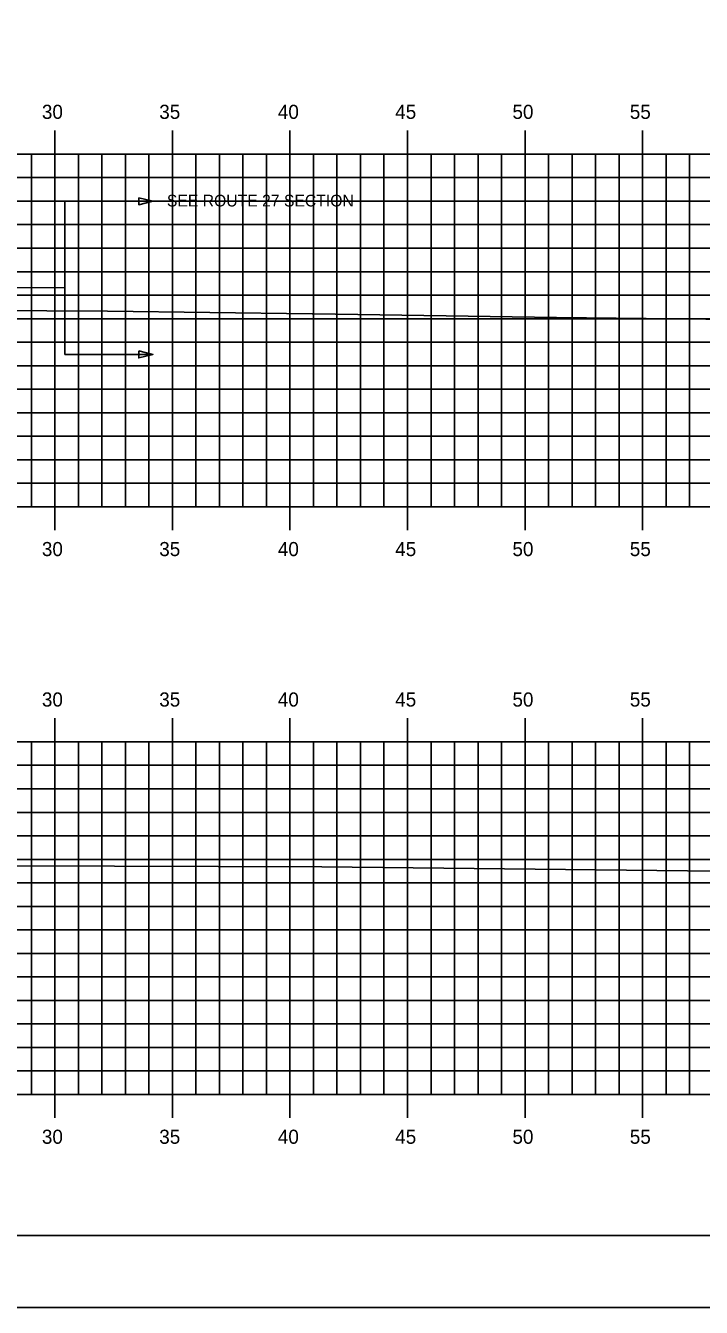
# Model space of a CAD drawing. Extents: x 1048109 to 1048279, y 781630 to 781740.
# Drawn here: x 1048220.5 to 1048249.2, y 781630.1 to 781684.7 of the extents above; entities that cross this region are included whole.
import ezdxf

# ---------------------------------------------------------------- set-up
doc = ezdxf.new("R2010")
doc.units = 0
for name, color, linetype in [('ANNOTATION', 7, 'Continuous'), ('D_Roadway_Centerline', 7, 'Continuous'), ('Default', 7, 'Continuous'), ('H_V ANNOTATION', 7, 'Continuous'), ('MAJOR', 7, 'Continuous'), ('MINOR', 7, 'Continuous'), ('S_Roadway_Centerline', 7, 'Continuous')]:
    doc.layers.add(name, color=color, linetype=linetype)

msp = doc.modelspace()

# ---------------------------------------------------------------- linework, layer by layer
at = {"layer": 'ANNOTATION'}
for p, q in [((1048225.901, 781677.193), (1048222.163, 781677.193)), ((1048225.901, 781670.675), (1048222.163, 781670.675))]:
    msp.add_line(p, q, dxfattribs=at)
for points in [[(1048225.301, 781677.343), (1048225.901, 781677.193), (1048225.301, 781677.043)], [(1048225.301, 781670.825), (1048225.901, 781670.675), (1048225.301, 781670.525)]]:
    msp.add_lwpolyline(points, close=True, dxfattribs=at)
at = {"layer": 'D_Roadway_Centerline'}
for p, q in [((1048222.163, 781670.675), (1048222.163, 781677.193)), ((1048191.733, 781673.663), (1048222.163, 781673.508))]:
    msp.add_line(p, q, dxfattribs=at)
at = {"layer": 'Default'}
msp.add_line((1048116.734, 781633.195), (1048276.734, 781633.195), dxfattribs=at)
msp.add_lwpolyline([(1048108.64, 781630.136), (1048278.64, 781630.136), (1048278.64, 781740.136), (1048108.64, 781740.136)], close=True, dxfattribs=at)
at = {"layer": 'MAJOR'}
for p, q in [((1048221.733, 781680.197), (1048221.733, 781679.195)), ((1048221.733, 781680.197), (1048221.733, 781679.195)), ((1048226.733, 781680.197), (1048226.733, 781679.195)), ((1048226.733, 781680.197), (1048226.733, 781679.195)), ((1048231.733, 781680.197), (1048231.733, 781679.195)), ((1048231.733, 781680.197), (1048231.733, 781679.195)), ((1048236.733, 781680.197), (1048236.733, 781679.195)), ((1048236.733, 781680.197), (1048236.733, 781679.195)), ((1048241.733, 781680.197), (1048241.733, 781679.195)), ((1048241.733, 781680.197), (1048241.733, 781679.195)), ((1048246.733, 781680.197), (1048246.733, 781679.195)), ((1048246.733, 781680.197), (1048246.733, 781679.195)), ((1048121.733, 781679.195), (1048261.733, 781679.195)), ((1048121.733, 781679.195), (1048261.733, 781679.195)), ((1048121.733, 781679.195), (1048261.733, 781679.195)), ((1048121.733, 781679.195), (1048261.733, 781679.195)), ((1048221.733, 781664.195), (1048221.733, 781679.195)), ((1048221.733, 781664.195), (1048221.733, 781679.195)), ((1048226.733, 781664.195), (1048226.733, 781679.195)), ((1048226.733, 781664.195), (1048226.733, 781679.195)), ((1048231.733, 781664.195), (1048231.733, 781679.195)), ((1048231.733, 781664.195), (1048231.733, 781679.195)), ((1048236.733, 781664.195), (1048236.733, 781679.195)), ((1048236.733, 781664.195), (1048236.733, 781679.195)), ((1048241.733, 781664.195), (1048241.733, 781679.195)), ((1048241.733, 781664.195), (1048241.733, 781679.195)), ((1048246.733, 781664.195), (1048246.733, 781679.195)), ((1048246.733, 781664.195), (1048246.733, 781679.195)), ((1048121.733, 781674.195), (1048261.733, 781674.195)), ((1048121.733, 781674.195), (1048261.733, 781674.195)), ((1048121.733, 781669.195), (1048261.733, 781669.195)), ((1048121.733, 781669.195), (1048261.733, 781669.195)), ((1048121.733, 781664.195), (1048261.733, 781664.195)), ((1048121.733, 781664.195), (1048261.733, 781664.195)), ((1048121.733, 781664.195), (1048261.733, 781664.195)), ((1048121.733, 781664.195), (1048261.733, 781664.195)), ((1048221.733, 781663.193), (1048221.733, 781664.195)), ((1048221.733, 781663.193), (1048221.733, 781664.195)), ((1048226.733, 781663.193), (1048226.733, 781664.195)), ((1048226.733, 781663.193), (1048226.733, 781664.195)), ((1048231.733, 781663.193), (1048231.733, 781664.195)), ((1048231.733, 781663.193), (1048231.733, 781664.195)), ((1048236.733, 781663.193), (1048236.733, 781664.195)), ((1048236.733, 781663.193), (1048236.733, 781664.195)), ((1048241.733, 781663.193), (1048241.733, 781664.195)), ((1048241.733, 781663.193), (1048241.733, 781664.195)), ((1048246.733, 781663.193), (1048246.733, 781664.195)), ((1048246.733, 781663.193), (1048246.733, 781664.195)), ((1048221.733, 781655.197), (1048221.733, 781654.195)), ((1048221.733, 781655.197), (1048221.733, 781654.195)), ((1048226.733, 781655.197), (1048226.733, 781654.195)), ((1048226.733, 781655.197), (1048226.733, 781654.195)), ((1048231.733, 781655.197), (1048231.733, 781654.195)), ((1048231.733, 781655.197), (1048231.733, 781654.195)), ((1048236.733, 781655.197), (1048236.733, 781654.195)), ((1048236.733, 781655.197), (1048236.733, 781654.195)), ((1048241.733, 781655.197), (1048241.733, 781654.195)), ((1048241.733, 781655.197), (1048241.733, 781654.195)), ((1048246.733, 781655.197), (1048246.733, 781654.195)), ((1048246.733, 781655.197), (1048246.733, 781654.195)), ((1048121.733, 781654.195), (1048261.733, 781654.195)), ((1048121.733, 781654.195), (1048261.733, 781654.195)), ((1048121.733, 781654.195), (1048261.733, 781654.195)), ((1048121.733, 781654.195), (1048261.733, 781654.195)), ((1048221.733, 781639.195), (1048221.733, 781654.195)), ((1048221.733, 781639.195), (1048221.733, 781654.195)), ((1048226.733, 781639.195), (1048226.733, 781654.195)), ((1048226.733, 781639.195), (1048226.733, 781654.195)), ((1048231.733, 781639.195), (1048231.733, 781654.195)), ((1048231.733, 781639.195), (1048231.733, 781654.195)), ((1048236.733, 781639.195), (1048236.733, 781654.195)), ((1048236.733, 781639.195), (1048236.733, 781654.195)), ((1048241.733, 781639.195), (1048241.733, 781654.195)), ((1048241.733, 781639.195), (1048241.733, 781654.195)), ((1048246.733, 781639.195), (1048246.733, 781654.195)), ((1048246.733, 781639.195), (1048246.733, 781654.195)), ((1048121.733, 781649.195), (1048261.733, 781649.195)), ((1048121.733, 781649.195), (1048261.733, 781649.195)), ((1048121.733, 781644.195), (1048261.733, 781644.195)), ((1048121.733, 781644.195), (1048261.733, 781644.195)), ((1048121.733, 781639.195), (1048261.733, 781639.195)), ((1048121.733, 781639.195), (1048261.733, 781639.195)), ((1048121.733, 781639.195), (1048261.733, 781639.195)), ((1048121.733, 781639.195), (1048261.733, 781639.195)), ((1048221.733, 781638.193), (1048221.733, 781639.195)), ((1048221.733, 781638.193), (1048221.733, 781639.195)), ((1048226.733, 781638.193), (1048226.733, 781639.195)), ((1048226.733, 781638.193), (1048226.733, 781639.195)), ((1048231.733, 781638.193), (1048231.733, 781639.195)), ((1048231.733, 781638.193), (1048231.733, 781639.195)), ((1048236.733, 781638.193), (1048236.733, 781639.195)), ((1048236.733, 781638.193), (1048236.733, 781639.195)), ((1048241.733, 781638.193), (1048241.733, 781639.195)), ((1048241.733, 781638.193), (1048241.733, 781639.195)), ((1048246.733, 781638.193), (1048246.733, 781639.195))]:
    msp.add_line(p, q, dxfattribs=at)
at = {"layer": 'MINOR'}
for p, q in [((1048220.733, 781664.195), (1048220.733, 781679.195)), ((1048220.733, 781664.195), (1048220.733, 781679.195)), ((1048222.733, 781664.195), (1048222.733, 781679.195)), ((1048222.733, 781664.195), (1048222.733, 781679.195)), ((1048223.733, 781664.195), (1048223.733, 781679.195)), ((1048223.733, 781664.195), (1048223.733, 781679.195)), ((1048224.733, 781664.195), (1048224.733, 781679.195)), ((1048224.733, 781664.195), (1048224.733, 781679.195)), ((1048225.733, 781664.195), (1048225.733, 781679.195)), ((1048225.733, 781664.195), (1048225.733, 781679.195)), ((1048227.733, 781664.195), (1048227.733, 781679.195)), ((1048227.733, 781664.195), (1048227.733, 781679.195)), ((1048228.733, 781664.195), (1048228.733, 781679.195)), ((1048228.733, 781664.195), (1048228.733, 781679.195)), ((1048229.733, 781664.195), (1048229.733, 781679.195)), ((1048229.733, 781664.195), (1048229.733, 781679.195)), ((1048230.733, 781664.195), (1048230.733, 781679.195)), ((1048230.733, 781664.195), (1048230.733, 781679.195)), ((1048232.733, 781664.195), (1048232.733, 781679.195)), ((1048232.733, 781664.195), (1048232.733, 781679.195)), ((1048233.733, 781664.195), (1048233.733, 781679.195)), ((1048233.733, 781664.195), (1048233.733, 781679.195)), ((1048234.733, 781664.195), (1048234.733, 781679.195)), ((1048234.733, 781664.195), (1048234.733, 781679.195)), ((1048235.733, 781664.195), (1048235.733, 781679.195)), ((1048235.733, 781664.195), (1048235.733, 781679.195)), ((1048237.733, 781664.195), (1048237.733, 781679.195)), ((1048237.733, 781664.195), (1048237.733, 781679.195)), ((1048238.733, 781664.195), (1048238.733, 781679.195)), ((1048238.733, 781664.195), (1048238.733, 781679.195)), ((1048239.733, 781664.195), (1048239.733, 781679.195)), ((1048239.733, 781664.195), (1048239.733, 781679.195)), ((1048240.733, 781664.195), (1048240.733, 781679.195)), ((1048240.733, 781664.195), (1048240.733, 781679.195)), ((1048242.733, 781664.195), (1048242.733, 781679.195)), ((1048242.733, 781664.195), (1048242.733, 781679.195)), ((1048243.733, 781664.195), (1048243.733, 781679.195)), ((1048243.733, 781664.195), (1048243.733, 781679.195)), ((1048244.733, 781664.195), (1048244.733, 781679.195)), ((1048244.733, 781664.195), (1048244.733, 781679.195)), ((1048245.733, 781664.195), (1048245.733, 781679.195)), ((1048245.733, 781664.195), (1048245.733, 781679.195)), ((1048247.733, 781664.195), (1048247.733, 781679.195)), ((1048247.733, 781664.195), (1048247.733, 781679.195)), ((1048248.733, 781664.195), (1048248.733, 781679.195)), ((1048248.733, 781664.195), (1048248.733, 781679.195)), ((1048121.733, 781678.195), (1048261.733, 781678.195)), ((1048121.733, 781678.195), (1048261.733, 781678.195)), ((1048121.733, 781677.195), (1048261.733, 781677.195)), ((1048121.733, 781677.195), (1048261.733, 781677.195)), ((1048121.733, 781676.195), (1048261.733, 781676.195)), ((1048121.733, 781676.195), (1048261.733, 781676.195)), ((1048121.733, 781675.195), (1048261.733, 781675.195)), ((1048121.733, 781675.195), (1048261.733, 781675.195)), ((1048121.733, 781673.195), (1048261.733, 781673.195)), ((1048121.733, 781673.195), (1048261.733, 781673.195)), ((1048121.733, 781672.195), (1048261.733, 781672.195)), ((1048121.733, 781672.195), (1048261.733, 781672.195)), ((1048121.733, 781671.195), (1048261.733, 781671.195)), ((1048121.733, 781671.195), (1048261.733, 781671.195)), ((1048121.733, 781670.195), (1048261.733, 781670.195)), ((1048121.733, 781670.195), (1048261.733, 781670.195)), ((1048121.733, 781668.195), (1048261.733, 781668.195)), ((1048121.733, 781668.195), (1048261.733, 781668.195)), ((1048121.733, 781667.195), (1048261.733, 781667.195)), ((1048121.733, 781667.195), (1048261.733, 781667.195)), ((1048121.733, 781666.195), (1048261.733, 781666.195)), ((1048121.733, 781666.195), (1048261.733, 781666.195)), ((1048121.733, 781665.195), (1048261.733, 781665.195)), ((1048121.733, 781665.195), (1048261.733, 781665.195)), ((1048220.733, 781639.195), (1048220.733, 781654.195)), ((1048220.733, 781639.195), (1048220.733, 781654.195)), ((1048222.733, 781639.195), (1048222.733, 781654.195)), ((1048222.733, 781639.195), (1048222.733, 781654.195)), ((1048223.733, 781639.195), (1048223.733, 781654.195)), ((1048223.733, 781639.195), (1048223.733, 781654.195)), ((1048224.733, 781639.195), (1048224.733, 781654.195)), ((1048224.733, 781639.195), (1048224.733, 781654.195)), ((1048225.733, 781639.195), (1048225.733, 781654.195)), ((1048225.733, 781639.195), (1048225.733, 781654.195)), ((1048227.733, 781639.195), (1048227.733, 781654.195)), ((1048227.733, 781639.195), (1048227.733, 781654.195)), ((1048228.733, 781639.195), (1048228.733, 781654.195)), ((1048228.733, 781639.195), (1048228.733, 781654.195)), ((1048229.733, 781639.195), (1048229.733, 781654.195)), ((1048229.733, 781639.195), (1048229.733, 781654.195)), ((1048230.733, 781639.195), (1048230.733, 781654.195)), ((1048230.733, 781639.195), (1048230.733, 781654.195)), ((1048232.733, 781639.195), (1048232.733, 781654.195)), ((1048232.733, 781639.195), (1048232.733, 781654.195)), ((1048233.733, 781639.195), (1048233.733, 781654.195)), ((1048233.733, 781639.195), (1048233.733, 781654.195)), ((1048234.733, 781639.195), (1048234.733, 781654.195)), ((1048234.733, 781639.195), (1048234.733, 781654.195)), ((1048235.733, 781639.195), (1048235.733, 781654.195)), ((1048235.733, 781639.195), (1048235.733, 781654.195)), ((1048237.733, 781639.195), (1048237.733, 781654.195)), ((1048237.733, 781639.195), (1048237.733, 781654.195)), ((1048238.733, 781639.195), (1048238.733, 781654.195)), ((1048238.733, 781639.195), (1048238.733, 781654.195)), ((1048239.733, 781639.195), (1048239.733, 781654.195)), ((1048239.733, 781639.195), (1048239.733, 781654.195)), ((1048240.733, 781639.195), (1048240.733, 781654.195)), ((1048240.733, 781639.195), (1048240.733, 781654.195)), ((1048242.733, 781639.195), (1048242.733, 781654.195)), ((1048242.733, 781639.195), (1048242.733, 781654.195)), ((1048243.733, 781639.195), (1048243.733, 781654.195)), ((1048243.733, 781639.195), (1048243.733, 781654.195)), ((1048244.733, 781639.195), (1048244.733, 781654.195)), ((1048244.733, 781639.195), (1048244.733, 781654.195)), ((1048245.733, 781639.195), (1048245.733, 781654.195)), ((1048245.733, 781639.195), (1048245.733, 781654.195)), ((1048247.733, 781639.195), (1048247.733, 781654.195)), ((1048247.733, 781639.195), (1048247.733, 781654.195)), ((1048248.733, 781639.195), (1048248.733, 781654.195)), ((1048248.733, 781639.195), (1048248.733, 781654.195)), ((1048121.733, 781653.195), (1048261.733, 781653.195)), ((1048121.733, 781653.195), (1048261.733, 781653.195)), ((1048121.733, 781652.195), (1048261.733, 781652.195)), ((1048121.733, 781652.195), (1048261.733, 781652.195)), ((1048121.733, 781651.195), (1048261.733, 781651.195)), ((1048121.733, 781651.195), (1048261.733, 781651.195)), ((1048121.733, 781650.195), (1048261.733, 781650.195)), ((1048121.733, 781650.195), (1048261.733, 781650.195)), ((1048121.733, 781648.195), (1048261.733, 781648.195)), ((1048121.733, 781648.195), (1048261.733, 781648.195)), ((1048121.733, 781647.195), (1048261.733, 781647.195)), ((1048121.733, 781647.195), (1048261.733, 781647.195)), ((1048121.733, 781646.195), (1048261.733, 781646.195)), ((1048121.733, 781646.195), (1048261.733, 781646.195)), ((1048121.733, 781645.195), (1048261.733, 781645.195)), ((1048121.733, 781645.195), (1048261.733, 781645.195)), ((1048121.733, 781643.195), (1048261.733, 781643.195)), ((1048121.733, 781643.195), (1048261.733, 781643.195)), ((1048121.733, 781642.195), (1048261.733, 781642.195)), ((1048121.733, 781642.195), (1048261.733, 781642.195)), ((1048121.733, 781641.195), (1048261.733, 781641.195)), ((1048121.733, 781641.195), (1048261.733, 781641.195)), ((1048121.733, 781640.195), (1048261.733, 781640.195)), ((1048121.733, 781640.195), (1048261.733, 781640.195))]:
    msp.add_line(p, q, dxfattribs=at)
at = {"layer": 'S_Roadway_Centerline'}
for points in [[(1048213.646, 781672.566), (1048223.979, 781672.514), (1048232.678, 781672.408), (1048232.733, 781672.406), (1048243.07, 781672.24), (1048257.031, 781672.083), (1048261.733, 781671.981)], [(1048121.733, 781648.883), (1048132.166, 781648.791), (1048158.795, 781649.038), (1048158.833, 781649.037), (1048162.032, 781649.025), (1048164.242, 781649.039), (1048164.257, 781649.038), (1048178.681, 781649.019), (1048190.522, 781649.013), (1048211.019, 781648.954), (1048233.093, 781648.88), (1048259.004, 781648.594), (1048261.733, 781648.51)]]:
    msp.add_lwpolyline(points, dxfattribs=at)

# ---------------------------------------------------------------- texts
at = {"layer": 'ANNOTATION'}
msp.add_text('SEE ROUTE 27 SECTION', height=0.5, dxfattribs=at).set_placement((1048226.498, 781676.968))
at = {"layer": 'H_V ANNOTATION'}
for s, p in [('30', (1048221.182, 781680.695)), ('35', (1048226.174, 781680.695)), ('40', (1048231.219, 781680.695)), ('45', (1048236.211, 781680.695)), ('50', (1048241.198, 781680.695)), ('55', (1048246.19, 781680.695)), ('30', (1048221.182, 781662.095)), ('35', (1048226.174, 781662.095)), ('40', (1048231.219, 781662.095)), ('45', (1048236.211, 781662.095)), ('50', (1048241.198, 781662.095)), ('55', (1048246.19, 781662.095)), ('30', (1048221.182, 781655.695)), ('35', (1048226.174, 781655.695)), ('40', (1048231.219, 781655.695)), ('45', (1048236.211, 781655.695)), ('50', (1048241.198, 781655.695)), ('55', (1048246.19, 781655.695)), ('30', (1048221.182, 781637.095)), ('35', (1048226.174, 781637.095)), ('40', (1048231.219, 781637.095)), ('45', (1048236.211, 781637.095)), ('50', (1048241.198, 781637.095)), ('55', (1048246.19, 781637.095))]:
    msp.add_text(s, height=0.6, dxfattribs=at).set_placement(p)

doc.saveas('drawing.dxf')
